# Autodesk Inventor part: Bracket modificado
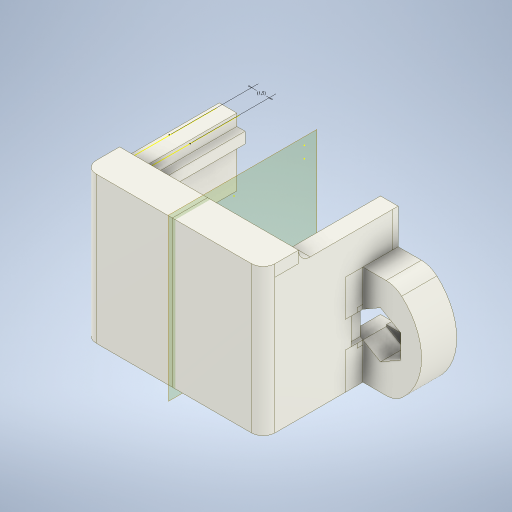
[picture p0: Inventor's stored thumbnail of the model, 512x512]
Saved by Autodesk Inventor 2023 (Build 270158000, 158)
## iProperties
Created: 2022-03
Part Number: Bracket modificado
Material: ABS Plastic
Document SubType Name: Modeling
Designer: Rosario
Density: 1.06 g/cm^3
Appearance: Valor por defecto
Mass: 0.871886 g
Surface Area: 12.0108 cm^2
Volume: 0.822534 cm^3
Sending System: Autodesk Translation Framework v10.13.0.1454
Preprocessor: ST-DEVELOPER v18.1
Title: F:/GrabCAD/Brackets for N20 gear motor/brackets.step
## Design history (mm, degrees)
node "Body1"
sketch "Boceto1"
  geometry: L1 (10.5, 3.5)-(12.5, 3.5); L2 (12.5, 3.5)-(12.5, 1.5); L3 (12.5, 1.5)-(10.5, 1.5); L4 (10.5, 1.5)-(10.5, 3.5); L5 (2.5, 3.5)-(0.5, 3.5); L6 (0.5, 3.5)-(0.5, 1.5); L7 (0.5, 1.5)-(2.5, 1.5); L8 (2.5, 1.5)-(2.5, 3.5); C1 r 2 at (10.5, 3.5); C2 r 1 at (11.5, 2.5); C3 r 2 at (2.5, 3.5); C4 r 1 at (1.5, 2.5); A1 r 2 centre (10.5, 3.5) between (10.5, 1.5) and (12.5, 3.5) reference; A2 r 2 centre (2.5, 3.5) between (0.5, 3.5) and (2.5, 1.5) reference; 9 further points
  constraints: 16 end point, 6 tangent, 4 centre point, 4 parallel, 2 coincident, 2 horizontal, 2 perpendicular
  dimensions: "d0" = 2 diameter of C2
extrude "Corrección radio superior" cut sketch "Boceto1" distance "d1" = 11.5; taper "d2" = 0 deg
sketch "Boceto2"
  geometry: L1 (1.984, 5.75)-(3.484, 5.75) reference; L2 (3.484, 5.75)-(3.484, 11.5) reference; L3 (1.984, 11.5)-(3.484, 11.5) reference; L4 (1.984, 8.5)-(1.984, 11.5) reference; L5 (1.984, 8.5)-(0, 8.5) reference; L6 (3.484, 0)-(0, 0) reference; L7 (3.484, 0)-(3.484, 2.75) reference; L8 (3.484, 2.75)-(1.984, 2.75) reference; L9 (1.984, 2.75)-(1.984, 3.25) reference; L10 (1.984, 3.25)-(0.484, 3.25) reference; L11 (0.484, 5.25)-(1.984, 5.25) reference; L12 (1.984, 5.25)-(1.984, 5.75) reference; L13 (16.984, 2.75)-(15.484, 2.75) reference; L14 (15.484, 0)-(15.484, 2.75) reference; L15 (15.484, 0)-(18.969, 0) reference; L16 (16.984, 8.5)-(18.969, 8.5) reference; L17 (16.984, 8.5)-(16.984, 11.5) reference; L18 (15.484, 11.5)-(16.984, 11.5) reference; L19 (15.484, 5.75)-(15.484, 11.5) reference; L20 (15.484, 5.75)-(16.984, 5.75) reference; L21 (16.984, 5.75)-(16.984, 5.25) reference; L22 (16.984, 5.25)-(18.484, 5.25) reference; L23 (18.484, 3.25)-(16.984, 3.25) reference; L24 (16.984, 3.25)-(16.984, 2.75) reference; A1 r 2 centre (0, 6.5) between (0, 8.5) and (-1.323, 8) reference; A2 r 5 centre (1.984, 4.25) between (-1.323, 8) and (-1.323, 0.5) reference; A3 r 2 centre (0, 2) between (-1.323, 0.5) and (0, 0) reference; A4 r 1 centre (0.484, 4.25) between (0.484, 5.25) and (0.484, 3.25) reference; A5 r 2 centre (18.969, 2) between (18.969, 0) and (20.292, 0.5) reference; A6 r 5 centre (16.984, 4.25) between (20.292, 0.5) and (20.292, 8) reference; A7 r 2 centre (18.969, 6.5) between (20.292, 8) and (18.969, 8.5) reference; A8 r 1 centre (18.484, 4.25) between (18.484, 3.25) and (18.484, 5.25) reference; 1 further point
extrude "Extrucción altura calce con motor" join sketch "Boceto2" distance "d3" = 0.5; taper "d4" = 0 deg
sketch "Boceto4"
  geometry: 1 further point
sketch "Boceto6"
  geometry: L1 (-1, 1)-(-1, 7) reference; L2 (14, 1)-(-1, 1); L3 (-1, 1)-(-1, 3); L4 (-1, 3)-(14, 3); L5 (14, 3)-(14, 1); L6 (11.5, 1.5)-(1.5, 1.5) reference; L7 (0.5, 2.5)-(0.5, 11.5) reference; L8 (-1, 11.5)-(0.5, 11.5) reference; L9 (-1, 11)-(-1, 11.5) reference; L10 (-1, 11)-(-1, 1) reference; L11 (0, 0)-(13, 0) reference; L12 (14, 1)-(14, 11) reference; L13 (14, 11)-(14, 11.5) reference; L14 (12.5, 11.5)-(14, 11.5) reference; L15 (12.5, 11.5)-(12.5, 2.5) reference; L16 (0, 0)-(13, 0); C1 r 1 at (0, 1); A1 r 1 centre (1.5, 2.5) between (0.5, 2.5) and (1.5, 1.5) reference; A2 r 1 centre (0, 1) between (-1, 1) and (0, 0) reference; A3 r 1 centre (13, 1) between (13, 0) and (14, 1) reference; A4 r 1 centre (11.5, 2.5) between (11.5, 1.5) and (12.5, 2.5) reference; A5 r 1 centre (13, 1) between (13, 0) and (14, 1); A6 r 1 centre (0, 1) between (-1, 1) and (0, 0); 7 further points
  constraints: 10 end point, 4 coincident, 4 point on circle, 3 centre point, 3 equal length, 1 concentric, 1 horizontal, 1 perpendicular, 1 point on line, 1 tangent, 1 vertical alignment, 4 other
  dimensions: "d42" = 1 radius of A3 (derived); "d43" = 1 radius of A2 (derived); "d44" = 3 distance between parallel lines of L4 L11
extrude "Contención frontal" join sketch "Boceto6" distance "d14" = 1; taper "d15" = 0 deg
sketch "Boceto7"
  geometry: L1 (-13.5, -0.5)-(-13.5, -10.5) reference; L2 (-12, -9)-(-12, 0) reference; 5 further points
  constraints: 2 point on line
  dimensions: "d16" = 1.5 horizontal distance of point (-13.5, -4.5) point (-12, -4.25) (derived)
sketch "Boceto11"
  geometry: L1 (-3.5, 3)-(-3.5, 8.75) reference; L2 (5.516, 7.757)-(-3.5, 7.757); L3 (-3.5, 7.757)-(-3.5, 6.81); L4 (-3.5, 6.81)-(5.516, 6.81); L5 (5.516, 6.81)-(5.516, 7.757); L6 (-3.5, 8.75)-(5.5, 8.75) reference; 3 further points
  constraints: 8 end point, 2 parallel, 1 horizontal, 1 perpendicular, 1 point on line
  dimensions: "d20" = 0.993 distance between parallel lines of L2 L6; "d21" = 0.947 distance between parallel lines of L4 L2
extrude "Ranura 1 izq" join sketch "Boceto11" distance "d22" = 0.697; taper "d23" = 0 deg
sketch "Boceto14"
  geometry: L1 (5.5, 6.81)-(5.5, -2.75) reference; L2 (5.5, 1.497)-(0, 1.497); L3 (0, 1.497)-(0, 0.55); L4 (0, 0.55)-(5.5, 0.55); L5 (5.5, 0.55)-(5.5, 1.497); L6 (5.516, 7.757)-(-3.5, 7.757) reference; 2 further points
  constraints: 8 end point, 2 parallel, 1 horizontal, 1 perpendicular, 1 point on line
  dimensions: "d29" = 7.207 distance between parallel lines of L4 L6; "d30" = 0.947 distance between parallel lines of L4 L2
extrude "Ranura 2 izq" join sketch "Boceto14" distance "d31" = 0.697; taper "d32" = 0 deg
sketch "Boceto15"
  geometry: 1 further point
sketch "Boceto16"
  geometry: 1 further point
sketch "Boceto17"
  geometry: L1 (-5.5, 8.75)-(-5.5, -2.75) reference; L2 (3.5, 8.75)-(3.5, 3) reference; L3 (-5.5, 6.81)-(3.5, 6.81); L4 (3.5, 6.81)-(3.5, 7.757); L5 (3.5, 7.757)-(-5.5, 7.757); L6 (-5.5, 7.757)-(-5.5, 6.81); L7 (-5.5, 8.75)-(3.5, 8.75) reference; 4 further points
  constraints: 8 end point, 2 parallel, 2 point on line, 1 horizontal, 1 perpendicular
  dimensions: "d33" = 0.993 distance between parallel lines of L5 L7; "d34" = 0.947 distance between parallel lines of L5 L3
extrude "Ranura 1 der" join sketch "Boceto17" distance "d35" = 0.697; taper "d36" = 0 deg
sketch "Soporte turca"
  geometry: L1 (0.5, 2.25)-(0, 2.539) reference; L2 (0, 0)-(0, 2.539) reference; L3 (0, 0)-(0.984, 0) reference; L4 (0.984, 8.5)-(0, 8.5) reference; L5 (0, 5.961)-(0, 8.5) reference; L6 (0, 5.961)-(0.5, 6.25) reference; L7 (0.5, 6.25)-(2.232, 5.25) reference; L8 (2.232, 5.25)-(2.232, 3.25) reference; L9 (2.232, 3.25)-(0.5, 2.25) reference; L10 (0, 2.539)-(-1, 3.116) reference; L11 (-1, 3.116)-(-1, 0) reference; L12 (-1, 0)-(0, 0) reference; L13 (0, 0)-(0, 2.539) reference; L14 (-1, 5.384)-(0, 5.961) reference; L15 (0, 5.961)-(0, 8.5) reference; L16 (0, 8.5)-(-1, 8.5) reference; L17 (-1, 8.5)-(-1, 5.384) reference; L18 (-16, 3.116)-(-17, 2.539) reference; L19 (-17, 2.539)-(-17, 0) reference; L20 (-17, 0)-(-16, 0) reference; L21 (-16, 0)-(-16, 3.116) reference; L22 (-17, 2.539)-(-17.5, 2.25) reference; L23 (-17.5, 2.25)-(-19.232, 3.25) reference; L24 (-19.232, 3.25)-(-19.232, 5.25) reference; L25 (-19.232, 5.25)-(-17.5, 6.25) reference; L26 (-17.5, 6.25)-(-17, 5.961) reference; L27 (-17, 8.5)-(-17, 5.961) reference; L28 (-17, 8.5)-(-17.984, 8.5) reference; L29 (-17.984, 0)-(-17, 0) reference; L30 (-17, 2.539)-(-17, 0) reference; L31 (-17, 5.961)-(-16, 5.384) reference; L32 (-16, 5.384)-(-16, 8.5) reference; L33 (-16, 8.5)-(-17, 8.5) reference; L34 (-17, 8.5)-(-17, 5.961) reference; A1 r 2 centre (0.984, 2) between (0.984, 0) and (2.307, 0.5) reference; A2 r 5 centre (-1, 4.25) between (2.307, 0.5) and (2.307, 8) reference; A3 r 2 centre (0.984, 6.5) between (2.307, 8) and (0.984, 8.5) reference; A4 r 2 centre (-17.984, 6.5) between (-17.984, 8.5) and (-19.307, 8) reference; A5 r 5 centre (-16, 4.25) between (-19.307, 8) and (-19.307, 0.5) reference; A6 r 2 centre (-17.984, 2) between (-19.307, 0.5) and (-17.984, 0) reference; 9 further points
  node "Contorno proyectado5"
  node "Contorno proyectado6"
  node "Contorno proyectado7"
  node "Contorno proyectado8"
  node "Contorno proyectado9"
  node "Contorno proyectado10"
sketch "Ranura turca"
  geometry: L1 (0, 0)-(0, 0.134) reference; L2 (1.5, 0)-(0, 0) reference; L3 (0, -2)-(1.5, -2) reference; L4 (0, -2.134)-(0, -2) reference; L5 (1.5, -3)-(0, -2.134) reference; L6 (3.232, -2)-(1.5, -3) reference; L7 (3.232, 0)-(3.232, -2) reference; L8 (1.5, 1)-(3.232, 0) reference; L9 (0, 0.134)-(1.5, 1) reference; L10 (-15, 0.134)-(-15, 0) reference; L11 (-15, 0.134)-(-16.5, 1) reference; L12 (-16.5, 1)-(-18.232, 0) reference; L13 (-18.232, 0)-(-18.232, -2) reference; L14 (-18.232, -2)-(-16.5, -3) reference; L15 (-16.5, -3)-(-15, -2.134) reference; L16 (-15, -2)-(-15, -2.134) reference; L17 (-15, -2)-(-16.5, -2) reference; L18 (-16.5, 0)-(-15, 0) reference; A1 r 1 centre (1.5, -1) between (1.5, -2) and (1.5, 0) reference; A2 r 1 centre (-16.5, -1) between (-16.5, 0) and (-16.5, -2) reference; 1 further point
  node "Contorno proyectado11"
  node "Contorno proyectado12"
feature "Empalme de cara1" dims "d45" = 1
feature "Empalme de cara2" dims "d46" = 1
sketch "Boceto22"
  geometry: L1 (0.697, 0)-(0.697, -0.947) reference; L2 (0.697, 0)-(0, 0) reference; L3 (0, -0.947)-(0, 0) reference; L4 (0.697, -0.947)-(0, -0.947) reference; L5 (0.697, 6.26)-(0.697, 5.313) reference; L6 (0.697, 6.26)-(0, 6.26) reference; L7 (0, 5.313)-(0, 6.26) reference; L8 (0.697, 5.313)-(0, 5.313) reference; L9 (-11.303, 6.26)-(-11.303, 5.313) reference; L10 (-11.303, 5.313)-(-10.606, 5.313) reference; L11 (-10.606, 6.26)-(-10.606, 5.313) reference; L12 (-11.303, 6.26)-(-10.606, 6.26) reference; 1 further point
extrude "Extenciones ranuras" join sketch "Boceto22" distance "d47" = 1; taper "d48" = 0 deg
extrude "Rebaje Soporte tuerca" cut sketch "Soporte turca" distance "d49" = 0.5; taper "d50" = 0 deg
extrude "Rebaje Encaje Tuerca" cut sketch "Ranura turca" distance "d51" = 0.5; taper "d52" = 0 deg
sketch "Boceto23"
  geometry: L1 (-1, 8.5)-(0.984, 8.5) reference; L2 (-1, 5.75)-(-1, 8.5) reference; L3 (-1, 5.384)-(-1, 5.75) reference; L4 (0.5, 6.25)-(-1, 5.384) reference; L5 (2.232, 5.25)-(0.5, 6.25) reference; L6 (2.232, 3.25)-(2.232, 5.25) reference; L7 (0.5, 2.25)-(2.232, 3.25) reference; L8 (-1, 3.116)-(0.5, 2.25) reference; L9 (-1, 2.75)-(-1, 3.116) reference; L10 (-1, 0)-(-1, 2.75) reference; L11 (0.984, 0)-(-1, 0) reference; L12 (-17.984, 8.5)-(-16, 8.5) reference; L13 (-16, 0)-(-17.984, 0) reference; L14 (-16, 2.75)-(-16, 0) reference; L15 (-16, 3.116)-(-16, 2.75) reference; L16 (-17.5, 2.25)-(-16, 3.116) reference; L17 (-19.232, 3.25)-(-17.5, 2.25) reference; L18 (-19.232, 5.25)-(-19.232, 3.25) reference; L19 (-17.5, 6.25)-(-19.232, 5.25) reference; L20 (-16, 5.384)-(-17.5, 6.25) reference; L21 (-16, 5.75)-(-16, 5.384) reference; L22 (-16, 8.5)-(-16, 5.75) reference; A1 r 2 centre (0.984, 2) between (0.984, 0) and (2.307, 0.5) reference; A2 r 5 centre (-1, 4.25) between (2.307, 0.5) and (2.307, 8) reference; A3 r 2 centre (0.984, 6.5) between (2.307, 8) and (0.984, 8.5) reference; A4 r 2 centre (-17.984, 6.5) between (-17.984, 8.5) and (-19.307, 8) reference; A5 r 5 centre (-16, 4.25) between (-19.307, 8) and (-19.307, 0.5) reference; A6 r 2 centre (-17.984, 2) between (-19.307, 0.5) and (-17.984, 0) reference; 1 further point
extrude "Eliminar empalme" cut sketch "Boceto23" distance "d53" = 1.5; taper "d54" = 0 deg
sketch "Boceto24"
  geometry: L1 (-0.232, -0.134)-(-0.232, -0.5) reference; L2 (-0.232, -0.5)-(1.268, -0.5) reference; L3 (1.268, 0.05)-(1.268, -0.5) reference; L4 (1.268, 0.05)-(1.965, 0.05) reference; L5 (1.965, 0.997)-(1.965, 0.05) reference; L6 (1.268, 0.997)-(1.965, 0.997) reference; L7 (1.268, 2.5)-(1.268, 0.997) reference; L8 (1.268, 2.5)-(-0.232, 2.5) reference; L9 (-0.232, 2.5)-(-0.232, 2.134) reference; L10 (0, 2)-(-0.232, 2.134) reference; L11 (0, 2)-(0, 0) reference; L12 (-0.232, -0.134)-(0, 0) reference; L13 (14.768, 2.134)-(14.768, 2.5) reference; L14 (13.268, 2.5)-(14.768, 2.5) reference; L15 (13.268, -0.5)-(13.268, 2.5) reference; L16 (14.768, -0.5)-(13.268, -0.5) reference; L17 (14.768, -0.5)-(14.768, -0.134) reference; L18 (14.536, 0)-(14.768, -0.134) reference; L19 (14.536, 0)-(14.536, 2) reference; L20 (14.768, 2.134)-(14.536, 2) reference; 1 further point
  node "Contorno proyectado21"
  node "Contorno proyectado22"
extrude "Corrección entrada tuerca 1" join sketch "Boceto24" distance "d55" = 0.5; taper "d56" = 0 deg
sketch "Boceto29"
  geometry: L1 (0, -3.25)-(0, -0.134) reference; L2 (6, -3.25)-(0, -3.25) reference; L3 (6, 9.25)-(6, -3.25) reference; L4 (4, 9.25)-(6, 9.25) reference; L5 (-4, 8.25)-(3, 8.25) reference; L6 (-4, 5.25)-(-4, 8.25) reference; L7 (-4, 5.25)-(-1.5, 5.25) reference; L8 (-1.5, 5.25)-(0, 5.25) reference; L9 (0, 2.134)-(0, 5.25) reference; L10 (0, -0.134)-(0, 2.134) reference; L11 (-1.5, -2.75)-(-1.5, 4.75) reference; L12 (-1.5, 4.75)-(-4.5, 4.75) reference; L13 (-4.5, -2.75)-(-4.5, 4.75) reference; L14 (-1.5, -2.75)-(-4.5, -2.75) reference; L15 (0, 2.134)-(-0.5, 2.134); L16 (-0.5, 2.134)-(-0.5, -0.134); L17 (-0.5, -0.134)-(0, -0.134); L18 (0, -0.134)-(0, 2.134); L19 (0, 2.134)-(-0.5, 2.134); L20 (-0.5, 2.134)-(-0.5, -0.134); L21 (-0.5, -0.134)-(0, -0.134); L22 (0, -0.134)-(0, 2.134); L23 (-1.5, -0.5)-(-1.5, -3.25) reference; L24 (0, -0.134)-(-1.5, -0.134); L25 (-1.5, -0.134)-(-1.5, -3.25); L26 (-1.5, -3.25)-(0, -3.25); L27 (0, -3.25)-(0, -0.134); L28 (0, 2.134)-(-1.5, 2.134); L29 (-1.5, 2.134)-(-1.5, 5.25); L30 (-1.5, 5.25)-(0, 5.25); L31 (0, 5.25)-(0, 2.134); A1 r 1 centre (3, 9.25) between (3, 8.25) and (4, 9.25) reference; 4 further points
  constraints: 32 end point, 8 parallel, 4 horizontal, 4 perpendicular
extrude "Corrección entrada tuerca izq" join sketch "Boceto29" stored distance "d57" = 10; taper "d58" = 0 deg
sketch "Boceto30"
  geometry: L1 (0, 5.25)-(0, 2.134) reference; L2 (0, 5.25)-(1.5, 5.25) reference; L3 (1.5, 5.25)-(4, 5.25) reference; L4 (4, 5.25)-(4, 8.25) reference; L5 (-3, 8.25)-(4, 8.25) reference; L6 (-4, 8.25)-(-4, 9.25) reference; L7 (-6, 8.25)-(-4, 8.25) reference; L8 (-6, -3.25)-(-6, 8.25) reference; L9 (0, -3.25)-(-6, -3.25) reference; L10 (0, -0.134)-(0, -3.25) reference; L11 (0, 2.134)-(0, -0.134) reference; L12 (1.5, 4.75)-(1.5, -2.75) reference; L13 (1.5, -2.75)-(4.5, -2.75) reference; L14 (4.5, 4.75)-(4.5, -2.75) reference; L15 (1.5, 4.75)-(4.5, 4.75) reference; L16 (0.5, -0.134)-(0, -0.134) reference; L17 (0, -0.134)-(0.5, -0.134); L18 (0.5, -0.134)-(0.5, 2.134); L19 (0.5, 2.134)-(0, 2.134); L20 (0, 2.134)-(0, -0.134); L21 (0, 2.134)-(0, 5.25) reference; L22 (4, 5.25)-(1.5, 5.25) reference; L23 (0, 2.134)-(1.5, 2.134); L24 (1.5, 2.134)-(1.5, 5.25); L25 (1.5, 5.25)-(0, 5.25); L26 (0, 5.25)-(0, 2.134); L27 (1.5, -0.5)-(1.5, -3.25) reference; L28 (0, -0.134)-(1.5, -0.134); L29 (1.5, -0.134)-(1.5, -3.25); L30 (1.5, -3.25)-(0, -3.25); L31 (0, -3.25)-(0, -0.134); A1 r 1 centre (-3, 9.25) between (-4, 9.25) and (-3, 8.25) reference; 5 further points
  constraints: 24 end point, 6 parallel, 3 perpendicular, 1 horizontal
extrude "Corrección entrada tuerca der" join sketch "Boceto30" stored distance "d59" = 10; taper "d60" = 0 deg
node "Plano de trabajo1"
feature "Dividir1"
  node "Sólido1"
node "Edición directa1"
sketch "Boceto31"
  geometry: L1 (-1.5, 11.5)-(-3, 11.5) reference; L2 (-1.5, 0)-(-1.5, 11.5) reference; L3 (0, 0)-(-1.5, 0) reference; L4 (0, 12.5)-(0, 0) reference; L5 (-3, 12.5)-(0, 12.5) reference; L6 (-3, 11.5)-(-3, 12.5) reference; 1 further point
extrude "Extrusión19" join sketch "Boceto31" distance "d64" = 0.25; taper "d65" = 0 deg
sketch "Boceto32"
  geometry: L1 (12.25, 0)-(6, 0) reference; L2 (12.25, 0)-(12.25, 0.5) reference; L3 (11.25, 1.5)-(6, 1.5) reference; L4 (6, 0)-(6, 1.5) reference; L5 (6, 1.5)-(6, 0) reference; L6 (6, 1.5)-(1, 1.5) reference; L7 (0, 0.5)-(0, 0) reference; L8 (6, 0)-(0, 0) reference; A1 r 1 centre (11.25, 0.5) between (12.25, 0.5) and (11.25, 1.5) reference; A2 r 1 centre (1, 0.5) between (1, 1.5) and (0, 0.5) reference; 3 further points
extrude "Extrusión20" cut sketch "Boceto32" distance "d66" = 0.1; taper "d67" = 0 deg
sketch "Boceto33"
  geometry: 1 further point
sketch "Boceto34"
  geometry: L1 (12.5, -3)-(6.25, -3) reference; L2 (12.5, -3)-(12.5, -2.5) reference; L3 (11.5, -1.5)-(6.25, -1.5) reference; L4 (6.25, -3)-(6.25, -1.5) reference; A1 r 1 centre (11.5, -2.5) between (12.5, -2.5) and (11.5, -1.5) reference; 1 further point
extrude "Extrusión21" cut sketch "Boceto34" distance "d68" = 0.1; taper "d69" = 0 deg
node "Contorno proyectado1"
node "Contorno proyectado2"
node "Contorno proyectado14"
node "Contorno proyectado15"
node "Contorno proyectado16"
node "Contorno proyectado18"
node "Contorno proyectado19"
node "Contorno proyectado20"
node "Contorno proyectado30"
node "Contorno proyectado31"
node "Contorno proyectado32"
node "Contorno proyectado33"
node "Contorno proyectado34"
node "Contorno proyectado35"
node "Contorno proyectado36"
node "Contorno proyectado37"
node "Sólido2"
node "Sólido3"
feature "Desplazar1" dims "d63" = 0.25
other parameters: "d61" = 0, "d62" = 0
